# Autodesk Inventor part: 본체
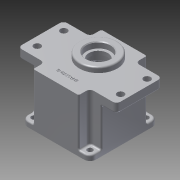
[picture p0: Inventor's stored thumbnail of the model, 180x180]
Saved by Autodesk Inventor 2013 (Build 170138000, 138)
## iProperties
Created: 2015-07
Part Number: 본체
Material: 알루미늄 6061
Document SubType Name: Modeling
Designer: user
Density: 1 g/cm^3
Author: user
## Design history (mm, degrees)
sketch "스케치1"
  geometry: L1 (-45, -45)-(45, -45); L2 (45, -45)-(45, 45); L3 (45, 45)-(-45, 45); L4 (-45, 45)-(-45, -45); L5 (-45, -45)-(45, 45); L6 (45, -45)-(-45, 45); 1 further point
  constraints: 12 end point, 2 midpoint, 2 parallel, 1 horizontal, 1 perpendicular
  dimensions: "d0" = 90 distance of L3.end L2.end; "d1" = 90 distance of L2.end L1.end
extrude "돌출1" new body sketch "스케치1" distance "d2" = 58; taper "d3" = 0 deg
sketch "스케치2"
  geometry: L1 (65, -45)-(-65, -45); L2 (-65, -45)-(-65, 45); L3 (-65, 45)-(65, 45); L4 (65, 45)-(65, -45); L5 (65, -45)-(-65, 45); L6 (-65, -45)-(65, 45); 1 further point
  constraints: 12 end point, 2 midpoint, 2 parallel, 1 horizontal, 1 perpendicular
  dimensions: "d4" = 130 distance of L2.end L3.end; "d5" = 90 distance of L1.end L2.end
extrude "돌출2" join sketch "스케치2" distance "d6" = 12; taper "d7" = 0 deg
sketch "스케치3"
  geometry: L1 (-65, -45)-(65, -45) reference; L2 (65, -45)-(65, 45) reference; L3 (-65, 45)-(-65, -45) reference; L4 (-30, 45)-(-30, 30); L5 (-30, 30)-(-65, 30); L6 (30, 45)-(30, 30); L7 (30, 30)-(65, 30); L8 (-65, 30)-(-65, 45); L9 (-30, 45)-(-65, 45); L10 (30, 45)-(65, 45); L11 (65, 30)-(65, 45); 2 further points
  constraints: 16 end point, 5 perpendicular, 2 collinear, 2 point on line, 1 parallel
  dimensions: "d9" = 60 distance of L4.start L6.start; "d10" = 15 distance of L4.start L4.end; "d12" = 15 distance of L6.start L6.end; "d13" = 35 distance between parallel lines of L2 L6; "d14" = 65 distance from line of point (0, 45) L2; "d15" = 90 distance from line of point (0, 45) L1
extrude "돌출3" cut sketch "스케치3" distance "d16" = 63; taper "d17" = 0 deg
sketch "스케치4"
  geometry: C1 r 40 at (0, 0); 1 further point
  constraints: 1 centre point, 1 coincident
  dimensions: "d18" = 80 diameter of C1
extrude "돌출4" cut sketch "스케치4" distance "d19" = 9; taper "d20" = 0 deg
sketch "스케치5" dims "d21" = 78
  geometry: L1 (0, 0)-(0, 35); L2 (0, 0)-(24.749, 24.749); C1 r 40 at (0, 0) reference; A1 r 4 centre (24.749, 24.749) between (21.809, 27.462) and (27.462, 21.809); A2 r 4 centre (24.749, -24.749) between (27.462, -21.809) and (21.809, -27.462); A3 r 4 centre (-24.749, -24.749) between (-21.809, -27.462) and (-27.462, -21.809); A4 r 4 centre (-24.749, 24.749) between (-27.462, 21.809) and (-21.809, 27.462); A5 r 3.5 centre (-29.836, 19.238) between (-27.412, 21.762) and (-32.777, 21.134); A6 r 3.5 centre (-19.238, 29.836) between (-21.134, 32.777) and (-21.762, 27.412); A7 r 3.5 centre (29.836, 19.238) between (32.777, 21.134) and (27.412, 21.762); A8 r 3.5 centre (19.238, -29.836) between (21.134, -32.777) and (21.762, -27.412); A9 r 3.5 centre (-19.238, -29.836) between (-21.762, -27.412) and (-21.134, -32.777); A10 r 3.5 centre (-29.836, -19.238) between (-32.777, -21.134) and (-27.412, -21.762); A11 r 3.5 centre (29.836, -19.238) between (27.412, -21.762) and (32.777, -21.134); A12 r 3.5 centre (19.238, 29.836) between (21.762, 27.412) and (21.134, 32.777); 1 further point
  constraints: 32 point on circle, 12 centre point, 8 tangent, 4 end point, 3 coincident, 1 point on line, 1 vertical, 22 other
  dimensions: "d23" = 45 deg angle of L2 L1; "d24" = 8 diameter of A1; "d25" = 8 diameter of A2; "d26" = 8 diameter of A3; "d27" = 8 diameter of A4; "d28" = 49.49747 distance of L2.end A2.centre; "d29" = 49.49747 distance of A4.centre L2.end; "d30" = 7 diameter of A5; "d31" = 7 diameter of A6; "d32" = 7 diameter of A7; "d33" = 7 diameter of A8; "d34" = 7 diameter of A9; "d35" = 7 diameter of A10; "d36" = 7 diameter of A11; "d37" = 7 diameter of A12; "d38" = 3.99472 distance from line of A7.end L2; "d39" = 34.77128 distance from line of A11.start L2; "d40" = 3.99472 distance from line of A12.start L2; "d41" = 34.77128 distance from line of A8.end L2; "d42" = 24.74874 distance from line of L1.end L2; "d43" = 34.77128 distance from line of A6.end L2; "d44" = 3.99472 distance from line of A9.start L2; "d45" = 34.77128 distance from line of A5.start L2; "d46" = 3.99472 distance from line of A10.end L2
extrude "돌출5" cut sketch "스케치5" distance "d47" = 52; taper "d48" = 0 deg
sketch "스케치6"
  geometry: L1 (30, 45)-(30, 30) reference; L2 (30, 30)-(65, 30) reference; L3 (65, 30)-(65, -30) reference; L4 (65, -30)-(30, -30) reference; L5 (30, -30)-(30, -45) reference; L6 (30, -45)-(-30, -45) reference; L7 (-30, -45)-(-30, -30) reference; L8 (-30, -30)-(-65, -30) reference; L9 (-65, -30)-(-65, 30) reference; L10 (-65, 30)-(-30, 30) reference; L11 (-30, 30)-(-30, 45) reference; L12 (-30, 45)-(30, 45) reference; L13 (-39, 0)-(39, 0); L14 (-126.492, 11)-(126.492, 11); L15 (-126.492, -20)-(126.492, -20); A1 r 4 centre (-24.749, 24.749) between (-27.462, 21.809) and (-21.809, 27.462) reference; A2 r 3.5 centre (-29.836, 19.238) between (-27.462, 21.809) and (-32.777, 21.134) reference; A3 r 39 centre (0, 0) between (-32.777, 21.134) and (-32.777, -21.134) reference; A4 r 3.5 centre (-29.836, -19.238) between (-32.777, -21.134) and (-27.462, -21.809) reference; A5 r 4 centre (-24.749, -24.749) between (-21.809, -27.462) and (-27.462, -21.809) reference; A6 r 3.5 centre (-19.238, -29.836) between (-21.809, -27.462) and (-21.134, -32.777) reference; A7 r 39 centre (0, 0) between (-21.134, -32.777) and (21.134, -32.777) reference; A8 r 3.5 centre (19.238, -29.836) between (21.134, -32.777) and (21.809, -27.462) reference; A9 r 4 centre (24.749, -24.749) between (27.462, -21.809) and (21.809, -27.462) reference; A10 r 3.5 centre (29.836, -19.238) between (27.462, -21.809) and (32.777, -21.134) reference; A11 r 39 centre (0, 0) between (32.777, -21.134) and (32.777, 21.134) reference; A12 r 3.5 centre (29.836, 19.238) between (32.777, 21.134) and (27.462, 21.809) reference; A13 r 4 centre (24.749, 24.749) between (21.809, 27.462) and (27.462, 21.809) reference; A14 r 3.5 centre (19.238, 29.836) between (21.809, 27.462) and (21.134, 32.777) reference; A15 r 39 centre (0, 0) between (21.134, 32.777) and (-21.134, 32.777) reference; A16 r 3.5 centre (-19.238, 29.836) between (-21.134, 32.777) and (-21.809, 27.462) reference; A17 r 20.5 centre (0, 11) between (7.402, -8.117) and (-7.402, -8.117); A18 r 14 centre (0, -20) between (-7.402, -8.117) and (7.402, -8.117)
  constraints: 6 end point, 6 point on circle, 2 centre point, 2 midpoint, 2 parallel
  dimensions: "d49" = 11 distance between parallel lines of L13 L14; "d51" = 20 distance between parallel lines of L15 L13; "d52" = 41 diameter of A17; "d53" = 28 diameter of A18
extrude "돌출6" join sketch "스케치6" distance "d54" = 7; taper "d55" = 0 deg
fillet "모깎기1" dims "d56" = 3
fillet "모깎기2" dims "d57" = 3
sketch "스케치7"
  geometry: C1 r 17.5 at (0, 11); A1 r 20.5 centre (0, 11) between (11.115, -6.225) and (-11.115, -6.225) reference; 1 further point
  constraints: 1 centre point, 1 coincident
  dimensions: "d58" = 35 diameter of C1
extrude "돌출7" cut sketch "스케치7" distance "d59" = 10; taper "d60" = 0 deg
sketch "스케치8"
  geometry: C1 r 17.5 at (0, 0) reference; C2 r 12.5 at (0, 0); 1 further point
  constraints: 1 centre point, 1 coincident
  dimensions: "d61" = 25 diameter of C2
extrude "돌출8" cut sketch "스케치8" distance "d62" = 5; taper "d63" = 0 deg
sketch "스케치9"
  geometry: C1 r 12.5 at (0, 0) reference; C2 r 16 at (0, 0); 1 further point
  constraints: 1 centre point, 1 coincident
  dimensions: "d64" = 32 diameter of C2
extrude "돌출9" cut sketch "스케치9" distance "d65" = 8; taper "d66" = 0 deg
sketch "스케치10"
  geometry: C1 r 16 at (0, 11) reference; C2 r 25 at (0, 11); 1 further point
  constraints: 1 centre point, 1 coincident
  dimensions: "d67" = 50 diameter of C2
extrude "돌출10" join sketch "스케치10" distance "d68" = 7; taper "d69" = 0 deg
sketch "스케치11"
  geometry: A1 r 4 centre (-24.749, 24.749) between (-27.462, 21.809) and (-21.809, 27.462) reference; A2 r 4 centre (24.749, 24.749) between (21.809, 27.462) and (27.462, 21.809) reference; A3 r 4 centre (24.749, -24.749) between (27.462, -21.809) and (21.809, -27.462) reference; A4 r 4 centre (-24.749, -24.749) between (-21.809, -27.462) and (-27.462, -21.809) reference
hole "구멍1" sketch "스케치11" at (-24.749, 24.749), (-24.749, -24.749), (24.749, -24.749), (24.749, 24.749) diameter "d70" = 3.459; stored, may be unused: countersink angle "d74" = 90 deg, drill point angle "d76" = 118 deg; dims "d71" = 12, "d72" = 4, "d73" = 2, "d75" = 15
fillet "모깎기3" dims "d77" = 8
sketch "스케치12"
  geometry: A1 r 8 centre (-37, 37) between (-37, 45) and (-45, 37) reference; A2 r 8 centre (-37, -37) between (-45, -37) and (-37, -45) reference; A3 r 8 centre (37, -37) between (37, -45) and (45, -37) reference; A4 r 8 centre (37, 37) between (45, 37) and (37, 45) reference
hole "구멍2" sketch "스케치12" at (-37, 37), (37, 37), (37, -37), (-37, -37) diameter "d78" = 7; stored, may be unused: countersink angle "d82" = 90 deg, drill point angle "d84" = 118 deg; dims "d79" = 12, "d80" = 4, "d81" = 2, "d83" = 15
fillet "모깎기4" dims "d85" = 5
sketch "스케치13"
  geometry: L1 (60, 30)-(30, 30) reference; L2 (65, -25)-(65, 25) reference; L3 (-53.488, -16.104)-(56.512, -16.104); L4 (56.512, -16.104)-(56.512, 18.896); L5 (56.512, 18.896)-(-53.488, 18.896); L6 (-53.488, 18.896)-(-53.488, -16.104); L7 (-53.488, -16.104)-(56.512, 18.896); L8 (56.512, -16.104)-(-53.488, 18.896); 6 further points
  constraints: 12 end point, 4 coincident, 2 midpoint, 2 parallel, 1 horizontal, 1 perpendicular
  dimensions: "d86" = 110 distance of L5.end L4.end; "d87" = 35 distance of L4.end L3.end; "d88" = 118.48778 distance between parallel lines of L2 L6; "d89" = 11.1041 distance between parallel lines of L1 L5
hole "구멍3" sketch "스케치13" at (-53.488, 18.896), (-53.488, -16.104), (56.512, -16.104), (56.512, 18.896) diameter "d90" = 9; stored, may be unused: countersink angle "d94" = 90 deg, drill point angle "d96" = 118 deg; dims "d91" = 12, "d92" = 4, "d93" = 2, "d95" = 15
sketch "스케치14"
  geometry: C1 r 11 at (0, -20); A1 r 14 centre (0, -20) between (-10.493, -10.732) and (10.493, -10.732) reference; 1 further point
  constraints: 1 centre point, 1 coincident
  dimensions: "d97" = 22 diameter of C1
extrude "돌출11" cut sketch "스케치14" distance "d98" = 7; taper "d99" = 0 deg
sketch "스케치15"
  geometry: C1 r 11 at (0, 0) reference; C2 r 9.5 at (0, 0); 1 further point
  constraints: 1 centre point, 1 coincident
  dimensions: "d100" = 19 diameter of C2
extrude "돌출12" cut sketch "스케치15" distance "d101" = 1; taper "d102" = 0 deg
fillet "모깎기6" dims "d104" = 2
chamfer "모따기1" distance "d105" = 1; stored, may be unused: second distance "d106" = 2, angle "d107" = 45 deg
chamfer "모따기2" distance "d108" = 1; stored, may be unused: second distance "d109" = 2, angle "d110" = 45 deg
fillet "모깎기8" dims "d112" = 2
fillet "모깎기9" dims "d113" = 2
sketch "스케치16"
  geometry: L1 (-30, -45)-(30, -45) reference; L2 (0, 11)-(0, -45); C1 r 25 at (0, 11) reference; 4 further points
  constraints: 2 end point, 1 midpoint, 1 point on line, 1 other
  dimensions: "d117" = 15 distance from line of L1 point (0, -30)
feature "엠보싱1" sketch "스케치16" dims "d118" = 0.5, "d119" = 0
fillet "모깎기13" dims "d120" = 2
fillet "모깎기14" dims "d121" = 5
fillet "모깎기15" dims "d122" = 5
fillet "모깎기16" dims "d123" = 2
fillet "모깎기17" dims "d124" = 2
fillet "모깎기19" dims "d126" = 0.3
fillet "모깎기20" dims "d127" = 0.3
fillet "모깎기21" dims "d128" = 2
fillet "모깎기22" dims "d129" = 2
node "솔리드1"
mirror "대칭1"
node "절단 모서리 투영1"
